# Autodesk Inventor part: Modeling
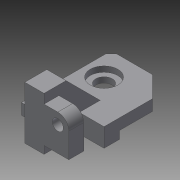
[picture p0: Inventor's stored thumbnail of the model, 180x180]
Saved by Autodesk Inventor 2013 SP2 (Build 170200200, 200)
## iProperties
Created: 2015-11
Part Number: Modeling
Material: 일반
Document SubType Name: Modeling
Designer: mys
Density: 1 g/cm^3
Author: mys
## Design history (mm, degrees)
sketch "스케치1"
  geometry: L1 (-95, 56.5)-(85, 56.5); L2 (95, 46.5)-(95, -18.5); L3 (57, -56.5)-(-95, -56.5); L4 (-95, -56.5)-(-95, 56.5); L5 (-95, 56.5)-(95, -56.5); L6 (95, 56.5)-(-95, -56.5); L7 (95, -18.5)-(57, -56.5); L8 (85, 56.5)-(95, 46.5); 1 further point
  constraints: 16 end point, 4 point on line, 2 midpoint, 2 parallel, 1 horizontal, 1 perpendicular
  dimensions: "d0" = 190 distance of L5.end L3.end; "d2" = 113 distance of L6.start L5.end; "d3" = 38 distance of L2.end L5.end; "d4" = 38 distance of L3.start L5.end (= d3); "d5" = 10 distance of L1.end L6.start; "d6" = 10 distance of L2.start L6.start (= d5)
extrude "돌출1" new body sketch "스케치1" distance "d7" = 20; taper "d8" = 0 deg
sketch "스케치2"
  geometry: L1 (-95, 18.5)-(-95, -46.5) reference; C1 r 25 at (-47, -21.5); 2 further points
  constraints: 1 centre point
  dimensions: "d9" = 48 distance from line of L1 C1.centre; "d10" = 78 vertical distance of point (-57, 56.5) C1.centre; "d11" = 50 diameter of C1
extrude "돌출2" cut sketch "스케치2" distance "d12" = 10; taper "d13" = 0 deg
sketch "스케치3"
  geometry: C1 r 25 at (0, 0) reference; C2 r 15 at (0, 0); 1 further point
  constraints: 1 centre point, 1 coincident
  dimensions: "d14" = 30 diameter of C2
extrude "돌출3" cut sketch "스케치3" distance "d16" = 32; taper "d17" = 0 deg
sketch "스케치4"
  geometry: L1 (152, 0)-(0, 0) reference; L2 (0, 20)-(152, 20) reference; L3 (190, 0)-(190, 20) reference; L4 (92, 0)-(64, 0); L5 (64, 0)-(64, -14); L6 (64, -14)-(92, -14); L7 (92, -14)-(92, 0); 1 further point
  constraints: 8 end point, 2 parallel, 1 horizontal, 1 perpendicular, 1 point on line
  dimensions: "d18" = 98 distance between parallel lines of L3 L7; "d19" = 28 distance of L5.end L6.end; "d20" = 34 distance between parallel lines of L6 L2
extrude "돌출4" join sketch "스케치4" distance "d21" = 113; taper "d22" = 0 deg
sketch "스케치5"
  geometry: L1 (95, -56.5)-(68, -56.5); L2 (68, -56.5)-(68, -23.5); L3 (68, -23.5)-(95, -23.5); L4 (95, -23.5)-(95, -56.5); 1 further point
  constraints: 8 end point, 2 parallel, 1 horizontal, 1 perpendicular
  dimensions: "d23" = 27 distance of L1.start L1.end; "d24" = 33 distance of L1.end L2.end
extrude "돌출5" cut sketch "스케치5" distance "d25" = 113; taper "d26" = 0 deg
sketch "스케치6"
  geometry: L1 (-95, 18.5)-(-95, -46.5) reference; L2 (95, 56.5)-(31, 56.5); L3 (31, 56.5)-(31, 11.5); L4 (31, 11.5)-(95, 11.5); L5 (95, 11.5)-(95, 56.5); 1 further point
  constraints: 8 end point, 2 parallel, 1 horizontal, 1 perpendicular
  dimensions: "d27" = 45 distance of L2.end L3.end; "d29" = 126 distance between parallel lines of L1 L3
extrude "돌출6" cut sketch "스케치6" distance "d30" = 113; taper "d31" = 0 deg
sketch "스케치7"
  geometry: L1 (0, 0)-(102, 0); L2 (40, 62)-(0, 62); L3 (0, 62)-(0, 0); L4 (64, -34)-(92, -34) reference; L5 (102, 0)-(40, 62); 1 further point
  constraints: 8 end point, 1 horizontal, 1 parallel, 1 vertical
  dimensions: "d32" = 96 distance between parallel lines of L4 L2; "d34" = 40 distance of L2.start L2.end; "d35" = 45 deg angle of L5 L2
extrude "돌출7" join sketch "스케치7" distance "d36" = 35; taper "d37" = 0 deg
sketch "스케치8"
  geometry: L1 (31, -11.5)-(95, -11.5) reference; L2 (95, -11.5)-(95, 23.5) reference; L3 (95, 23.5)-(31, 23.5); L4 (31, 23.5)-(31, -11.5); L5 (31, -11.5)-(95, -11.5); L6 (95, -11.5)-(95, 23.5); 1 further point
  constraints: 8 end point, 2 parallel, 1 horizontal, 1 perpendicular
extrude "돌출8" join sketch "스케치8" distance "d38" = 14; taper "d39" = 0 deg
sketch "스케치9"
  geometry: L1 (80, 34)-(80, 0) reference; L2 (35, 34)-(80, 34) reference; L3 (35, 34)-(80, 34); L4 (80, 34)-(80, 59) reference; L5 (60, 79)-(35, 79); L6 (35, 79)-(35, 34); L7 (80, 0)-(35, 0) reference; A1 r 20 centre (60, 59) between (80, 59) and (60, 79); 1 further point
  constraints: 8 end point, 2 parallel, 2 point on circle, 2 tangent, 1 centre point, 1 horizontal, 1 perpendicular, 1 vertical
  dimensions: "d40" = 20 radius of A1; "d41" = 59 distance from line of L7 A1.centre; "d42" = 45 distance of L2.start L1.start (derived)
extrude "돌출9" join sketch "스케치9" distance "d43" = 27; taper "d44" = 0 deg
sketch "스케치11"
  geometry: C1 r 10 at (-60, 59); A1 r 20 centre (-60, 59) between (-60, 79) and (-80, 59) reference; 1 further point
  constraints: 1 centre point, 1 coincident
  dimensions: "d48" = 20 diameter of C1
extrude "돌출10" cut sketch "스케치11" stored distance "d49" = 27; taper "d50" = 0 deg
sketch "스케치12"
  geometry: L1 (0, 45)-(0, 0) reference; L2 (-27, 45)-(0, 45) reference; L3 (-27, 45)-(0, 45); L4 (0, 45)-(0, 0); L5 (0, 0)-(-27, 0); L6 (-27, 0)-(-27, 45); 1 further point
  constraints: 8 end point, 2 parallel, 1 horizontal, 1 perpendicular
extrude "돌출11" join sketch "스케치12" distance "d51" = 20; taper "d52" = 0 deg
node "솔리드1"
